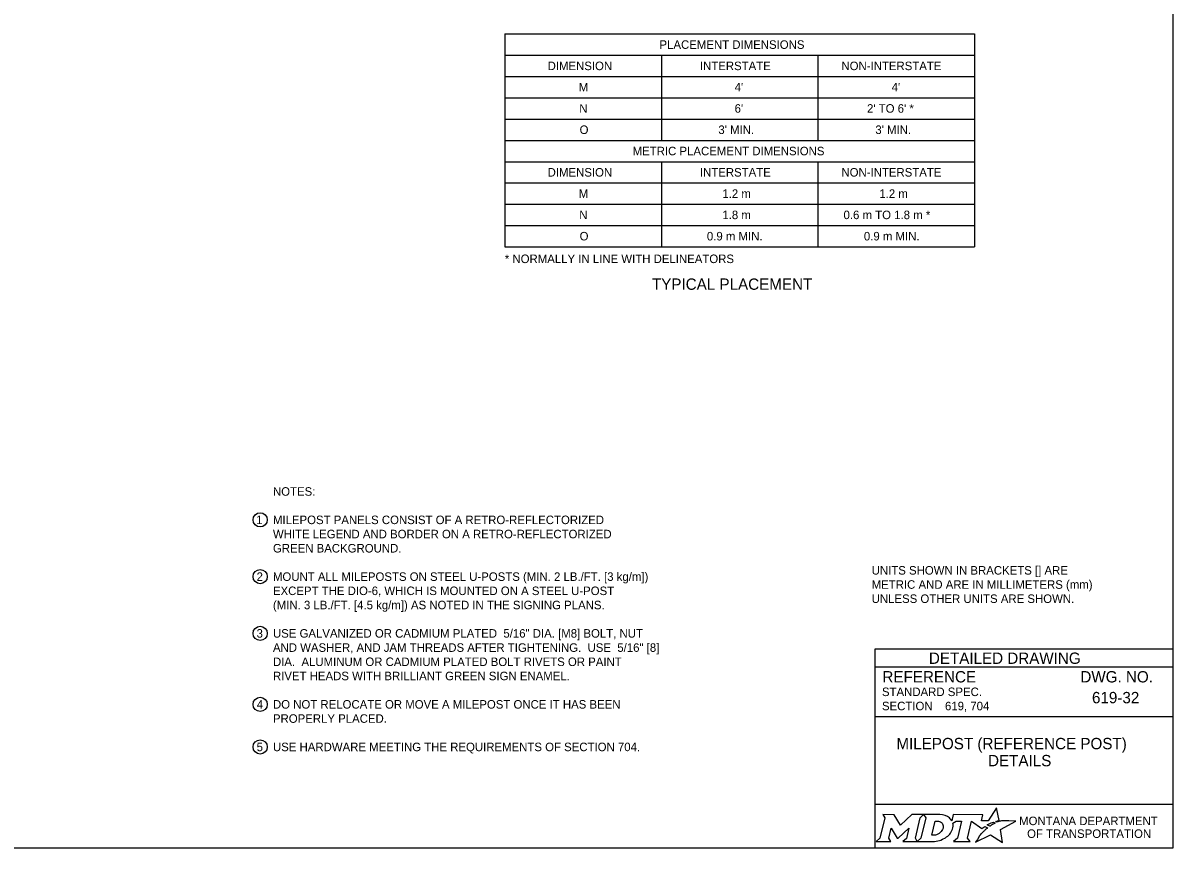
# Model space of a CAD drawing. Extents: x 49991.4 to 50021, y 49987.6 to 50011.4.
# Drawn here: x 50008.65 to 50016.75, y 49987.8 to 49993.61 of the extents above; entities that cross this region are included whole.
import ezdxf

# ---------------------------------------------------------------- set-up
doc = ezdxf.new("R2010")
doc.units = 0
for name, color, linetype in [('Default', 7, 'Continuous'), ('Level 1', 7, 'Continuous'), ('Level 2', 7, 'Continuous'), ('Level 5', 7, 'Continuous')]:
    doc.layers.add(name, color=color, linetype=linetype)

msp = doc.modelspace()

# ---------------------------------------------------------------- linework, layer by layer
at = {"layer": 'Default'}
for points in [[(50014.7056, 49988.0338), (50014.7197, 49988.0104), (50014.6862, 49987.8671), (50014.6605, 49987.8446), (50014.7621, 49987.8446), (50014.7486, 49987.8674), (50014.7648, 49987.9375), (50014.8085, 49987.8685), (50014.8138, 49987.8685), (50014.8889, 49987.938), (50014.8725, 49987.8669), (50014.8478, 49987.8449), (50014.9494, 49987.8449), (50014.9356, 49987.8682), (50014.9688, 49988.0106)], [(50014.9688, 49988.0106), (50014.9941, 49988.0338), (50014.9117, 49988.0338), (50014.8321, 49987.9608), (50014.7876, 49988.0335), (50014.7056, 49988.0338)], [(50015.1077, 49988.0338), (50014.9941, 49988.0338), (50015.0088, 49988.0109), (50014.9749, 49987.8671), (50014.9494, 49987.8449), (50015.06, 49987.8449)], [(50015.5126, 49987.9811), (50015.5023, 49987.9867), (50015.5139, 49987.9895), (50015.5255, 49987.9915), (50015.5081, 49988.0816), (50015.4486, 49987.9903), (50015.4013, 49987.9896), (50015.4116, 49988.0337), (50015.2024, 49988.0338), (50015.1923, 49987.9913), (50015.1865, 49987.9996)], [(50015.1317, 49987.9471), (50015.1305, 49987.939), (50015.1273, 49987.9297), (50015.1231, 49987.9215), (50015.1175, 49987.914), (50015.111, 49987.9071), (50015.1031, 49987.9008), (50015.0948, 49987.8961), (50015.0857, 49987.8922), (50015.0766, 49987.8899), (50015.0674, 49987.889), (50015.0515, 49987.889), (50015.0751, 49987.989), (50015.0911, 49987.989), (50015.0987, 49987.9884), (50015.1063, 49987.9865), (50015.1129, 49987.9835), (50015.119, 49987.9793), (50015.1238, 49987.9743), (50015.1275, 49987.9683), (50015.1302, 49987.9621), (50015.1318, 49987.9547), (50015.1318, 49987.9517), (50015.1317, 49987.9471)], [(50015.1991, 49987.9747), (50015.2237, 49987.9878), (50015.2606, 49987.9878), (50015.232, 49987.8673), (50015.2045, 49987.8446), (50015.3207, 49987.8446), (50015.3037, 49987.8675), (50015.3319, 49987.9877), (50015.4032, 49987.936), (50015.4243, 49987.9511), (50015.444, 49987.9402)], [(50015.3882, 49987.8843), (50015.3729, 49987.8599), (50015.3682, 49987.8524), (50015.3624, 49987.8438), (50015.3601, 49987.8395), (50015.4654, 49987.8926), (50015.5493, 49987.8375), (50015.5362, 49987.9302), (50015.6431, 49987.9886), (50015.5938, 49987.9894), (50015.5637, 49987.9898), (50015.5429, 49987.9901), (50015.5361, 49987.9886), (50015.5312, 49987.9874), (50015.5228, 49987.9851), (50015.5126, 49987.9811)], [(50015.4622, 49987.9535), (50015.4598, 49987.9518), (50015.4415, 49987.9614), (50015.4518, 49987.9671), (50015.4559, 49987.9693), (50015.4645, 49987.9733), (50015.4702, 49987.9759), (50015.4781, 49987.9789), (50015.4854, 49987.9816), (50015.4972, 49987.9742), (50015.4932, 49987.9721), (50015.4886, 49987.9696), (50015.4844, 49987.9674), (50015.4794, 49987.9645), (50015.4775, 49987.9634), (50015.4748, 49987.9618), (50015.4723, 49987.9604), (50015.47, 49987.9588), (50015.4674, 49987.957), (50015.4647, 49987.9552), (50015.4622, 49987.9535)], [(50015.1057, 49987.8522), (50015.1141, 49987.8548), (50015.1271, 49987.8602), (50015.1475, 49987.8712)], [(50015.4021, 49987.9004), (50015.4021, 49987.9004)]]:
    msp.add_lwpolyline(points, dxfattribs=at)
for centre, radius, start, end in [((50015.1308, 49987.9554), 0.0709, 339.53292, 15.85821), ((50015.0868, 49987.9727), 0.1183, 300.91025, 339.13831)]:
    msp.add_arc(centre, radius, start, end, dxfattribs=at)
for centre, major_axis, ratio, start_param, end_param in [((50015.1056, 49987.9864), (0.0834, -0.0037), 0.568097, 0.61298, 1.570796), ((50015.1612, 49987.9937), (0.0361, -0.0295), 0.469099, 1.225588, 1.570796), ((50015.4329, 49987.9305), (-0.0112, -0.0097), 0.021651, 3.157348, 6.283185), ((50015.3952, 49987.8923), (-0.00694, -0.00806), 0.008222, 0, 3.137361), ((50015.4119, 49987.9106), (-0.0098, -0.0102), 0.016458, 3.141593, 6.279097), ((50015.0603, 49987.9932), (0, 0.1484), 0.987302, 3.139398, 3.456847)]:
    msp.add_ellipse(centre, major_axis=major_axis, ratio=ratio, start_param=start_param, end_param=end_param, dxfattribs=at)
at = {"layer": 'Level 1'}
msp.add_lwpolyline([(49999.3835, 49998.9992), (50016.7501, 49998.9992), (50016.7501, 49987.7988), (49999.3835, 49987.7988)], close=True, dxfattribs=at)
at = {"layer": 'Level 2'}
for p, q in [((50012.0447, 49993.5351), (50012.0447, 49992.7851)), ((50012.0447, 49993.5351), (50015.3522, 49993.5351)), ((50015.3522, 49993.5351), (50015.3522, 49992.7851)), ((50012.0447, 49993.3851), (50015.3522, 49993.3851)), ((50013.1472, 49993.3851), (50013.1472, 49992.7851)), ((50014.2497, 49993.3851), (50014.2497, 49992.7851)), ((50012.0447, 49993.2351), (50015.3522, 49993.2351)), ((50012.0447, 49993.0851), (50015.3522, 49993.0851)), ((50012.0447, 49992.9351), (50015.3522, 49992.9351)), ((50012.0447, 49992.7851), (50015.3522, 49992.7851)), ((50012.0447, 49992.7851), (50012.0447, 49992.0351)), ((50015.3522, 49992.7851), (50015.3522, 49992.0351)), ((50012.0447, 49992.6351), (50015.3522, 49992.6351)), ((50013.1472, 49992.6351), (50013.1472, 49992.0351)), ((50014.2497, 49992.6351), (50014.2497, 49992.0351)), ((50012.0447, 49992.4851), (50015.3522, 49992.4851)), ((50012.0447, 49992.3351), (50015.3522, 49992.3351)), ((50012.0447, 49992.1851), (50015.3522, 49992.1851)), ((50012.0447, 49992.0351), (50015.3522, 49992.0351))]:
    msp.add_line(p, q, dxfattribs=at)
for centre in [(50010.3216, 49990.1111), (50010.3216, 49989.7111), (50010.3216, 49989.3111), (50010.3216, 49988.8111), (50010.3216, 49988.5111)]:
    msp.add_circle(centre, 0.05, dxfattribs=at)
at = {"layer": 'Level 5'}
for p, q in [((50016.7501, 49989.1988), (50014.6501, 49989.1988)), ((50014.6501, 49989.1988), (50014.6501, 49987.7988)), ((50016.7501, 49989.0738), (50014.6501, 49989.0738)), ((50016.3862, 49988.8587), (50016.3862, 49988.8587)), ((50015.1444, 49988.7993), (50015.1444, 49988.7993)), ((50016.7501, 49988.7238), (50014.6501, 49988.7238)), ((50015.7001, 49988.4747), (50015.7001, 49988.4747)), ((50016.7501, 49988.1057), (50014.6501, 49988.1057))]:
    msp.add_line(p, q, dxfattribs=at)

# ---------------------------------------------------------------- texts
at = {"layer": 'Default'}
for s, p in [('MONTANA DEPARTMENT', (50015.6663, 49987.96)), ('OF TRANSPORTATION', (50015.7225, 49987.87))]:
    msp.add_text(s, height=0.06, dxfattribs=at).set_placement(p)
at = {"layer": 'Level 2'}
for s, height, p in [('PLACEMENT DIMENSIONS', 0.06, (50013.1338, 49993.4301)), ('DIMENSION', 0.06, (50012.3457, 49993.2801)), ('INTERSTATE', 0.06, (50013.4183, 49993.2801)), ('NON-INTERSTATE', 0.06, (50014.415, 49993.2801)), ('M', 0.06, (50012.5654, 49993.1301)), ("4'", 0.06, (50013.6628, 49993.1301)), ("4'", 0.06, (50014.7684, 49993.1301)), ('N', 0.06, (50012.5689, 49992.9801)), ("6'", 0.06, (50013.6628, 49992.9801)), ("   2' TO 6' *", 0.06, (50014.5284, 49992.9801)), ('O', 0.06, (50012.5712, 49992.8301)), ("3' MIN.", 0.06, (50013.5483, 49992.8301)), ("3' MIN.", 0.06, (50014.6539, 49992.8301)), ('METRIC PLACEMENT DIMENSIONS', 0.06, (50012.9447, 49992.6801)), ('DIMENSION', 0.06, (50012.3457, 49992.5301)), ('INTERSTATE', 0.06, (50013.4183, 49992.5301)), ('NON-INTERSTATE', 0.06, (50014.415, 49992.5301)), ('M', 0.06, (50012.5654, 49992.3801)), ('1.2 m', 0.06, (50013.5766, 49992.3801)), ('1.2 m', 0.06, (50014.6822, 49992.3801)), ('N', 0.06, (50012.5689, 49992.2301)), ('1.8 m', 0.06, (50013.5766, 49992.2301)), ('0.6 m TO 1.8 m *', 0.06, (50014.4298, 49992.2301)), ('O', 0.06, (50012.5712, 49992.0801)), ('0.9 m MIN.', 0.06, (50013.4676, 49992.0801)), ('0.9 m MIN.', 0.06, (50014.5732, 49992.0801)), ('* NORMALLY IN LINE WITH DELINEATORS', 0.06, (50012.0447, 49991.9205)), ('TYPICAL PLACEMENT', 0.08, (50013.0805, 49991.7321)), ('NOTES:', 0.06, (50010.4116, 49990.2811)), ('1', 0.06, (50010.2929, 49990.0811)), ('MILEPOST PANELS CONSIST OF A RETRO-REFLECTORIZED', 0.06, (50010.4116, 49990.0811)), ('WHITE LEGEND AND BORDER ON A RETRO-REFLECTORIZED', 0.06, (50010.4116, 49989.9811)), ('GREEN BACKGROUND.', 0.06, (50010.4116, 49989.8811)), ('2', 0.06, (50010.2965, 49989.6811)), ('MOUNT ALL MILEPOSTS ON STEEL U-POSTS (MIN. 2 LB./FT. [3 kg/m])', 0.06, (50010.4116, 49989.6811)), ('UNITS SHOWN IN BRACKETS [] ARE ', 0.06, (50014.628, 49989.7255)), ('EXCEPT THE DIO-6, WHICH IS MOUNTED ON A STEEL U-POST', 0.06, (50010.4116, 49989.5811)), ('METRIC AND ARE IN MILLIMETERS (mm) ', 0.06, (50014.628, 49989.6255)), ('UNLESS OTHER UNITS ARE SHOWN.', 0.06, (50014.628, 49989.5255)), ('(MIN. 3 LB./FT. [4.5 kg/m]) AS NOTED IN THE SIGNING PLANS.', 0.06, (50010.4116, 49989.4811)), ('3', 0.06, (50010.2964, 49989.2811)), ('USE GALVANIZED OR CADMIUM PLATED  5/16" DIA. [M8] BOLT, NUT', 0.06, (50010.4116, 49989.2811)), ('AND WASHER, AND JAM THREADS AFTER TIGHTENING.  USE  5/16" [8]', 0.06, (50010.4116, 49989.1811)), ('DIA.  ALUMINUM OR CADMIUM PLATED BOLT RIVETS OR PAINT', 0.06, (50010.4116, 49989.0811)), ('RIVET HEADS WITH BRILLIANT GREEN SIGN ENAMEL.', 0.06, (50010.4116, 49988.9811)), ('4', 0.06, (50010.2977, 49988.7811)), ('DO NOT RELOCATE OR MOVE A MILEPOST ONCE IT HAS BEEN', 0.06, (50010.4116, 49988.7811)), ('619, 704', 0.06, (50015.1444, 49988.7693)), ('619-32', 0.08, (50016.1796, 49988.8187)), ('PROPERLY PLACED.', 0.06, (50010.4116, 49988.6811)), ('5', 0.06, (50010.2967, 49988.4811)), ('USE HARDWARE MEETING THE REQUIREMENTS OF SECTION 704. ', 0.06, (50010.4116, 49988.4811)), ('MILEPOST (REFERENCE POST)', 0.08, (50014.802, 49988.4947)), ('DETAILS', 0.08, (50015.4476, 49988.3747))]:
    msp.add_text(s, height=height, dxfattribs=at).set_placement(p)
at = {"layer": 'Level 5'}
for s, height, p in [('DETAILED DRAWING', 0.0799, (50015.0311, 49989.0963)), ('REFERENCE', 0.08, (50014.7037, 49988.9654)), ('DWG. NO.', 0.08, (50016.0979, 49988.9654)), ('STANDARD SPEC.', 0.06, (50014.7004, 49988.8694)), ('SECTION', 0.06, (50014.7004, 49988.7694))]:
    msp.add_text(s, height=height, dxfattribs=at).set_placement(p)

doc.saveas('drawing.dxf')
